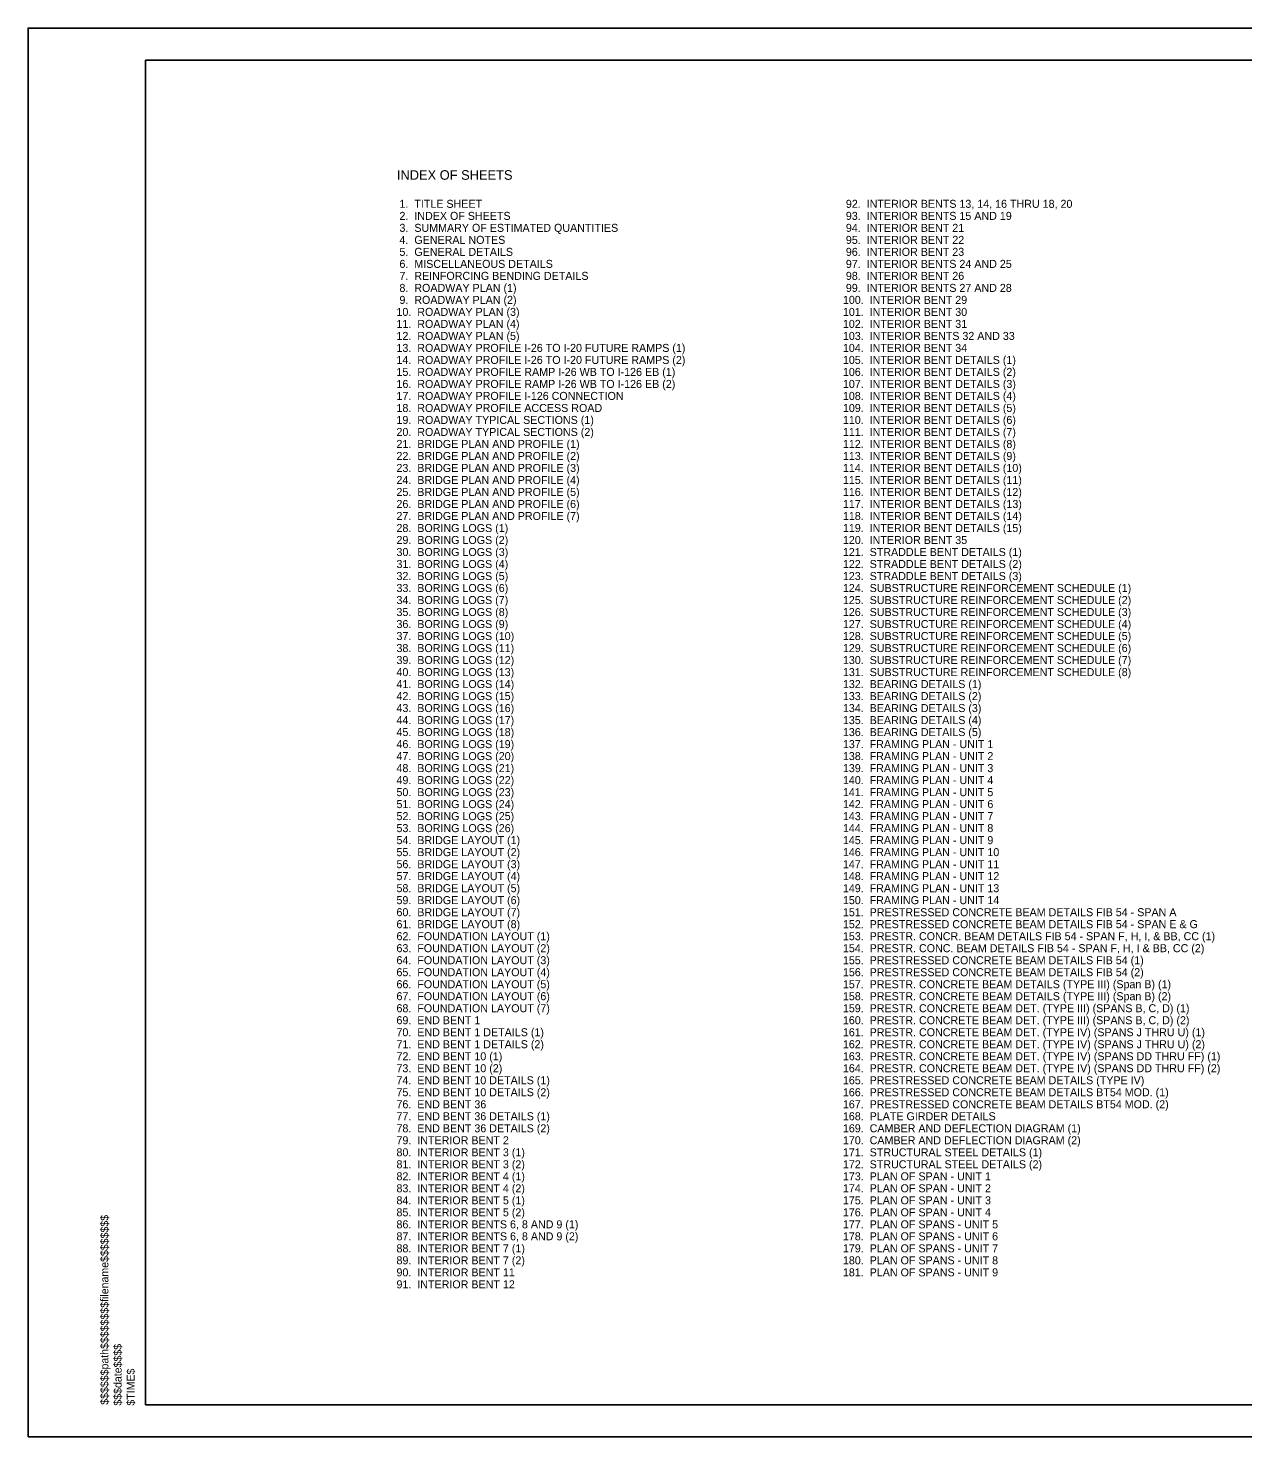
# Model space of a CAD drawing. Extents: x -125.5 to -89.4, y -5.1 to 16.9.
# Drawn here: x -125.53 to -106.56, y -5.07 to 16.93 of the extents above; entities that cross this region are included whole.
import ezdxf

# ---------------------------------------------------------------- set-up
doc = ezdxf.new("R2010")
doc.units = 0
for name, color, linetype in [('BR_AUTO DIMENSION', 7, 'Continuous'), ('BR_BORDER LINES', 7, 'Continuous'), ('BR_TEXT', 7, 'Continuous'), ('Level 31', 7, 'Continuous'), ('RD_SHT_ID', 7, 'Continuous')]:
    doc.layers.add(name, color=color, linetype=linetype)

msp = doc.modelspace()

# ---------------------------------------------------------------- linework, layer by layer
at = {"layer": 'BR_BORDER LINES'}
for p, q in [((-90.033, 16.434), (-123.699, 16.434)), ((-123.699, -4.566), (-123.699, 16.434)), ((-123.699, -4.566), (-90.033, -4.566))]:
    msp.add_line(p, q, dxfattribs=at)
at = {"layer": 'Level 31'}
msp.add_lwpolyline([(-125.533, -5.066), (-89.533, -5.066), (-89.533, 16.934), (-125.533, 16.934)], close=True, dxfattribs=at)

# ---------------------------------------------------------------- texts
at = {"layer": 'BR_AUTO DIMENSION'}
msp.add_text('INDEX OF SHEETS', height=0.15, dxfattribs=at).set_placement((-119.772, 14.566))
at = {"layer": 'BR_TEXT'}
for s, p in [(' 1.  TITLE SHEET', (-119.779, 14.128)), (' 92.  INTERIOR BENTS 13, 14, 16 THRU 18, 20', (-112.805, 14.128)), (' 3.  SUMMARY OF ESTIMATED QUANTITIES', (-119.779, 13.753)), (' 2.  INDEX OF SHEETS', (-119.779, 13.94)), (' 93.  INTERIOR BENTS 15 AND 19', (-112.805, 13.94)), (' 94.  INTERIOR BENT 21', (-112.805, 13.753)), (' 4.  GENERAL NOTES', (-119.779, 13.565)), (' 95.  INTERIOR BENT 22', (-112.805, 13.565)), (' 5.  GENERAL DETAILS', (-119.779, 13.378)), (' 96.  INTERIOR BENT 23', (-112.805, 13.378)), (' 6.  MISCELLANEOUS DETAILS', (-119.779, 13.19)), (' 97.  INTERIOR BENTS 24 AND 25', (-112.805, 13.19)), (' 7.  REINFORCING BENDING DETAILS', (-119.779, 13.003)), (' 98.  INTERIOR BENT 26', (-112.805, 13.003)), (' 8.  ROADWAY PLAN (1)', (-119.779, 12.815)), (' 99.  INTERIOR BENTS 27 AND 28', (-112.805, 12.815)), ('10.  ROADWAY PLAN (3)', (-119.779, 12.44)), (' 9.  ROADWAY PLAN (2)', (-119.779, 12.628)), ('100.  INTERIOR BENT 29', (-112.805, 12.628)), ('101.  INTERIOR BENT 30', (-112.805, 12.44)), ('11.  ROADWAY PLAN (4)', (-119.779, 12.253)), ('102.  INTERIOR BENT 31', (-112.805, 12.253)), ('12.  ROADWAY PLAN (5)', (-119.779, 12.065)), ('103.  INTERIOR BENTS 32 AND 33', (-112.805, 12.065)), ('13.  ROADWAY PROFILE I-26 TO I-20 FUTURE RAMPS (1)', (-119.779, 11.878)), ('104.  INTERIOR BENT 34', (-112.805, 11.878)), ('14.  ROADWAY PROFILE I-26 TO I-20 FUTURE RAMPS (2)', (-119.779, 11.69)), ('105.  INTERIOR BENT DETAILS (1)', (-112.805, 11.69)), ('15.  ROADWAY PROFILE RAMP I-26 WB TO I-126 EB (1)', (-119.779, 11.503)), ('16.  ROADWAY PROFILE RAMP I-26 WB TO I-126 EB (2)', (-119.779, 11.315)), ('106.  INTERIOR BENT DETAILS (2)', (-112.805, 11.503)), ('107.  INTERIOR BENT DETAILS (3)', (-112.805, 11.315)), ('17.  ROADWAY PROFILE I-126 CONNECTION', (-119.779, 11.128)), ('108.  INTERIOR BENT DETAILS (4)', (-112.805, 11.128)), ('18.  ROADWAY PROFILE ACCESS ROAD', (-119.779, 10.94)), ('109.  INTERIOR BENT DETAILS (5)', (-112.805, 10.94)), ('19.  ROADWAY TYPICAL SECTIONS (1)', (-119.779, 10.753)), ('110.  INTERIOR BENT DETAILS (6)', (-112.805, 10.753)), ('20.  ROADWAY TYPICAL SECTIONS (2)', (-119.779, 10.565)), ('111.  INTERIOR BENT DETAILS (7)', (-112.805, 10.565)), ('21.  BRIDGE PLAN AND PROFILE (1)', (-119.779, 10.378)), ('112.  INTERIOR BENT DETAILS (8)', (-112.805, 10.378)), ('22.  BRIDGE PLAN AND PROFILE (2)', (-119.779, 10.19)), ('23.  BRIDGE PLAN AND PROFILE (3)', (-119.779, 10.003)), ('113.  INTERIOR BENT DETAILS (9)', (-112.805, 10.19)), ('114.  INTERIOR BENT DETAILS (10)', (-112.805, 10.003)), ('24.  BRIDGE PLAN AND PROFILE (4)', (-119.779, 9.815)), ('115.  INTERIOR BENT DETAILS (11)', (-112.805, 9.815)), ('25.  BRIDGE PLAN AND PROFILE (5)', (-119.779, 9.628)), ('116.  INTERIOR BENT DETAILS (12)', (-112.805, 9.628)), ('26.  BRIDGE PLAN AND PROFILE (6)', (-119.779, 9.44)), ('117.  INTERIOR BENT DETAILS (13)', (-112.805, 9.44)), ('27.  BRIDGE PLAN AND PROFILE (7)', (-119.779, 9.253)), ('118.  INTERIOR BENT DETAILS (14)', (-112.805, 9.253)), ('28.  BORING LOGS (1)', (-119.779, 9.065)), ('119.  INTERIOR BENT DETAILS (15)', (-112.805, 9.065)), ('30.  BORING LOGS (3)', (-119.779, 8.69)), ('29.  BORING LOGS (2)', (-119.779, 8.878)), ('120.  INTERIOR BENT 35', (-112.805, 8.878)), ('121.  STRADDLE BENT DETAILS (1)', (-112.805, 8.69)), ('31.  BORING LOGS (4)', (-119.779, 8.503)), ('122.  STRADDLE BENT DETAILS (2)', (-112.805, 8.503)), ('32.  BORING LOGS (5)', (-119.779, 8.315)), ('123.  STRADDLE BENT DETAILS (3)', (-112.805, 8.315)), ('33.  BORING LOGS (6)', (-119.779, 8.128)), ('124.  SUBSTRUCTURE REINFORCEMENT SCHEDULE (1)', (-112.805, 8.128)), ('34.  BORING LOGS (7)', (-119.779, 7.94)), ('125.  SUBSTRUCTURE REINFORCEMENT SCHEDULE (2)', (-112.805, 7.94)), ('35.  BORING LOGS (8)', (-119.779, 7.753)), ('126.  SUBSTRUCTURE REINFORCEMENT SCHEDULE (3)', (-112.805, 7.753)), ('36.  BORING LOGS (9)', (-119.779, 7.565)), ('37.  BORING LOGS (10)', (-119.779, 7.378)), ('127.  SUBSTRUCTURE REINFORCEMENT SCHEDULE (4)', (-112.805, 7.565)), ('128.  SUBSTRUCTURE REINFORCEMENT SCHEDULE (5)', (-112.805, 7.378)), ('38.  BORING LOGS (11)', (-119.779, 7.19)), ('129.  SUBSTRUCTURE REINFORCEMENT SCHEDULE (6)', (-112.805, 7.19)), ('39.  BORING LOGS (12)', (-119.779, 7.003)), ('130.  SUBSTRUCTURE REINFORCEMENT SCHEDULE (7)', (-112.805, 7.003)), ('40.  BORING LOGS (13)', (-119.779, 6.815)), ('131.  SUBSTRUCTURE REINFORCEMENT SCHEDULE (8)', (-112.805, 6.815)), ('41.  BORING LOGS (14)', (-119.779, 6.628)), ('132.  BEARING DETAILS (1)', (-112.805, 6.628)), ('42.  BORING LOGS (15)', (-119.779, 6.44)), ('43.  BORING LOGS (16)', (-119.779, 6.253)), ('133.  BEARING DETAILS (2)', (-112.805, 6.44)), ('134.  BEARING DETAILS (3)', (-112.805, 6.253)), ('44.  BORING LOGS (17)', (-119.779, 6.065)), ('135.  BEARING DETAILS (4)', (-112.805, 6.065)), ('45.  BORING LOGS (18)', (-119.779, 5.878)), ('136.  BEARING DETAILS (5)', (-112.805, 5.878)), ('46.  BORING LOGS (19)', (-119.779, 5.69)), ('137.  FRAMING PLAN - UNIT 1', (-112.805, 5.69)), ('47.  BORING LOGS (20)', (-119.779, 5.503)), ('138.  FRAMING PLAN - UNIT 2', (-112.805, 5.503)), ('48.  BORING LOGS (21)', (-119.779, 5.315)), ('139.  FRAMING PLAN - UNIT 3', (-112.805, 5.315)), ('49.  BORING LOGS (22)', (-119.779, 5.128)), ('50.  BORING LOGS (23)', (-119.779, 4.94)), ('140.  FRAMING PLAN - UNIT 4', (-112.805, 5.128)), ('141.  FRAMING PLAN - UNIT 5', (-112.805, 4.94)), ('51.  BORING LOGS (24)', (-119.779, 4.753)), ('142.  FRAMING PLAN - UNIT 6', (-112.805, 4.753)), ('52.  BORING LOGS (25)', (-119.779, 4.565)), ('143.  FRAMING PLAN - UNIT 7', (-112.805, 4.565)), ('53.  BORING LOGS (26)', (-119.779, 4.378)), ('144.  FRAMING PLAN - UNIT 8', (-112.805, 4.378)), ('54.  BRIDGE LAYOUT (1)', (-119.779, 4.19)), ('145.  FRAMING PLAN - UNIT 9', (-112.805, 4.19)), ('55.  BRIDGE LAYOUT (2)', (-119.779, 4.003)), ('146.  FRAMING PLAN - UNIT 10', (-112.805, 4.003)), ('56.  BRIDGE LAYOUT (3)', (-119.779, 3.815)), ('57.  BRIDGE LAYOUT (4)', (-119.779, 3.628)), ('147.  FRAMING PLAN - UNIT 11', (-112.805, 3.815)), ('148.  FRAMING PLAN - UNIT 12', (-112.805, 3.628)), ('58.  BRIDGE LAYOUT (5)', (-119.779, 3.44)), ('149.  FRAMING PLAN - UNIT 13', (-112.805, 3.44)), ('59.  BRIDGE LAYOUT (6)', (-119.779, 3.253)), ('150.  FRAMING PLAN - UNIT 14', (-112.805, 3.253)), ('60.  BRIDGE LAYOUT (7)', (-119.779, 3.065)), ('151.  PRESTRESSED CONCRETE BEAM DETAILS FIB 54 - SPAN A', (-112.805, 3.065)), ('61.  BRIDGE LAYOUT (8)', (-119.779, 2.878)), ('152.  PRESTRESSED CONCRETE BEAM DETAILS FIB 54 - SPAN E & G', (-112.805, 2.878)), ('62.  FOUNDATION LAYOUT (1)', (-119.779, 2.69)), ('153.  PRESTR. CONCR. BEAM DETAILS FIB 54 - SPAN F, H, I, & BB, CC (1)', (-112.805, 2.69)), ('63.  FOUNDATION LAYOUT (2)', (-119.779, 2.503)), ('64.  FOUNDATION LAYOUT (3)', (-119.779, 2.315)), ('154.  PRESTR. CONC. BEAM DETAILS FIB 54 - SPAN F, H, I & BB, CC (2)', (-112.805, 2.503)), ('155.  PRESTRESSED CONCRETE BEAM DETAILS FIB 54 (1)', (-112.805, 2.315)), ('65.  FOUNDATION LAYOUT (4)', (-119.779, 2.128)), ('156.  PRESTRESSED CONCRETE BEAM DETAILS FIB 54 (2)', (-112.805, 2.128)), ('66.  FOUNDATION LAYOUT (5)', (-119.779, 1.94)), ('157.  PRESTR. CONCRETE BEAM DETAILS (TYPE III) (Span B) (1)', (-112.805, 1.94)), ('67.  FOUNDATION LAYOUT (6)', (-119.779, 1.753)), ('158.  PRESTR. CONCRETE BEAM DETAILS (TYPE III) (Span B) (2)', (-112.805, 1.753)), ('68.  FOUNDATION LAYOUT (7)', (-119.779, 1.565)), ('159.  PRESTR. CONCRETE BEAM DET. (TYPE III) (SPANS B, C, D) (1)', (-112.805, 1.565)), ('69.  END BENT 1', (-119.779, 1.378)), ('70.  END BENT 1 DETAILS (1)', (-119.779, 1.19)), ('160.  PRESTR. CONCRETE BEAM DET. (TYPE III) (SPANS B, C, D) (2)', (-112.805, 1.378)), ('161.  PRESTR. CONCRETE BEAM DET. (TYPE IV) (SPANS J THRU U) (1)', (-112.805, 1.19)), ('71.  END BENT 1 DETAILS (2)', (-119.779, 1.003)), ('162.  PRESTR. CONCRETE BEAM DET. (TYPE IV) (SPANS J THRU U) (2)', (-112.805, 1.003)), ('72.  END BENT 10 (1)', (-119.779, 0.815)), ('163.  PRESTR. CONCRETE BEAM DET. (TYPE IV) (SPANS DD THRU FF) (1)', (-112.805, 0.815)), ('73.  END BENT 10 (2)', (-119.779, 0.628)), ('164.  PRESTR. CONCRETE BEAM DET. (TYPE IV) (SPANS DD THRU FF) (2)', (-112.805, 0.628)), ('74.  END BENT 10 DETAILS (1)', (-119.779, 0.44)), ('165.  PRESTRESSED CONCRETE BEAM DETAILS (TYPE IV)', (-112.805, 0.44)), ('75.  END BENT 10 DETAILS (2)', (-119.779, 0.253)), ('166.  PRESTRESSED CONCRETE BEAM DETAILS BT54 MOD. (1)', (-112.805, 0.253)), ('76.  END BENT 36', (-119.779, 0.065)), ('77.  END BENT 36 DETAILS (1)', (-119.779, -0.122)), ('167.  PRESTRESSED CONCRETE BEAM DETAILS BT54 MOD. (2)', (-112.805, 0.065)), ('168.  PLATE GIRDER DETAILS', (-112.805, -0.122)), ('78.  END BENT 36 DETAILS (2)', (-119.779, -0.31)), ('169.  CAMBER AND DEFLECTION DIAGRAM (1)', (-112.805, -0.31)), ('79.  INTERIOR BENT 2', (-119.779, -0.497)), ('170.  CAMBER AND DEFLECTION DIAGRAM (2)', (-112.805, -0.497)), ('80.  INTERIOR BENT 3 (1)', (-119.779, -0.685)), ('171.  STRUCTURAL STEEL DETAILS (1)', (-112.805, -0.685)), ('81.  INTERIOR BENT 3 (2)', (-119.779, -0.872)), ('172.  STRUCTURAL STEEL DETAILS (2)', (-112.805, -0.872)), ('82.  INTERIOR BENT 4 (1)', (-119.779, -1.06)), ('173.  PLAN OF SPAN - UNIT 1', (-112.805, -1.06)), ('83.  INTERIOR BENT 4 (2)', (-119.779, -1.247)), ('84.  INTERIOR BENT 5 (1)', (-119.779, -1.435)), ('174.  PLAN OF SPAN - UNIT 2', (-112.805, -1.247)), ('175.  PLAN OF SPAN - UNIT 3', (-112.805, -1.435)), ('85.  INTERIOR BENT 5 (2)', (-119.779, -1.622)), ('176.  PLAN OF SPAN - UNIT 4', (-112.805, -1.622)), ('86.  INTERIOR BENTS 6, 8 AND 9 (1)', (-119.779, -1.81)), ('177.  PLAN OF SPANS - UNIT 5', (-112.805, -1.81)), ('87.  INTERIOR BENTS 6, 8 AND 9 (2)', (-119.779, -1.997)), ('178.  PLAN OF SPANS - UNIT 6', (-112.805, -1.997)), ('88.  INTERIOR BENT 7 (1)', (-119.779, -2.185)), ('179.  PLAN OF SPANS - UNIT 7', (-112.805, -2.185)), ('89.  INTERIOR BENT 7 (2)', (-119.779, -2.372)), ('180.  PLAN OF SPANS - UNIT 8', (-112.805, -2.372)), ('90.  INTERIOR BENT 11', (-119.779, -2.56)), ('91.  INTERIOR BENT 12', (-119.779, -2.747)), ('181.  PLAN OF SPANS - UNIT 9', (-112.805, -2.56))]:
    msp.add_text(s, height=0.125, dxfattribs=at).set_placement(p)
at = {"layer": 'RD_SHT_ID'}
for s, height, p in [('$$$$$$path$$$$$$$$filename$$$$$$$$', 0.12347, (-124.279, -4.566)), ('$$$date$$$$', 0.12347, (-124.073, -4.579)), ('$TIME$', 0.1235, (-123.869, -4.579))]:
    msp.add_text(s, height=height, rotation=90, dxfattribs=at).set_placement(p)

doc.saveas('drawing.dxf')
